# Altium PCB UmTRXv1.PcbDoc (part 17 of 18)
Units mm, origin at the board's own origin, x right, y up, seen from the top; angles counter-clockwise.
Board outline 172 x 113 mm, 6 copper layers (Top Layer, GND, MidLayer1, Mid-Layer 2, InternalPlane2, Bottom Layer); 766 components, 613 nets, 3008 pads, 1360 vias.
Unrouted connection lines stored in the file: 2.
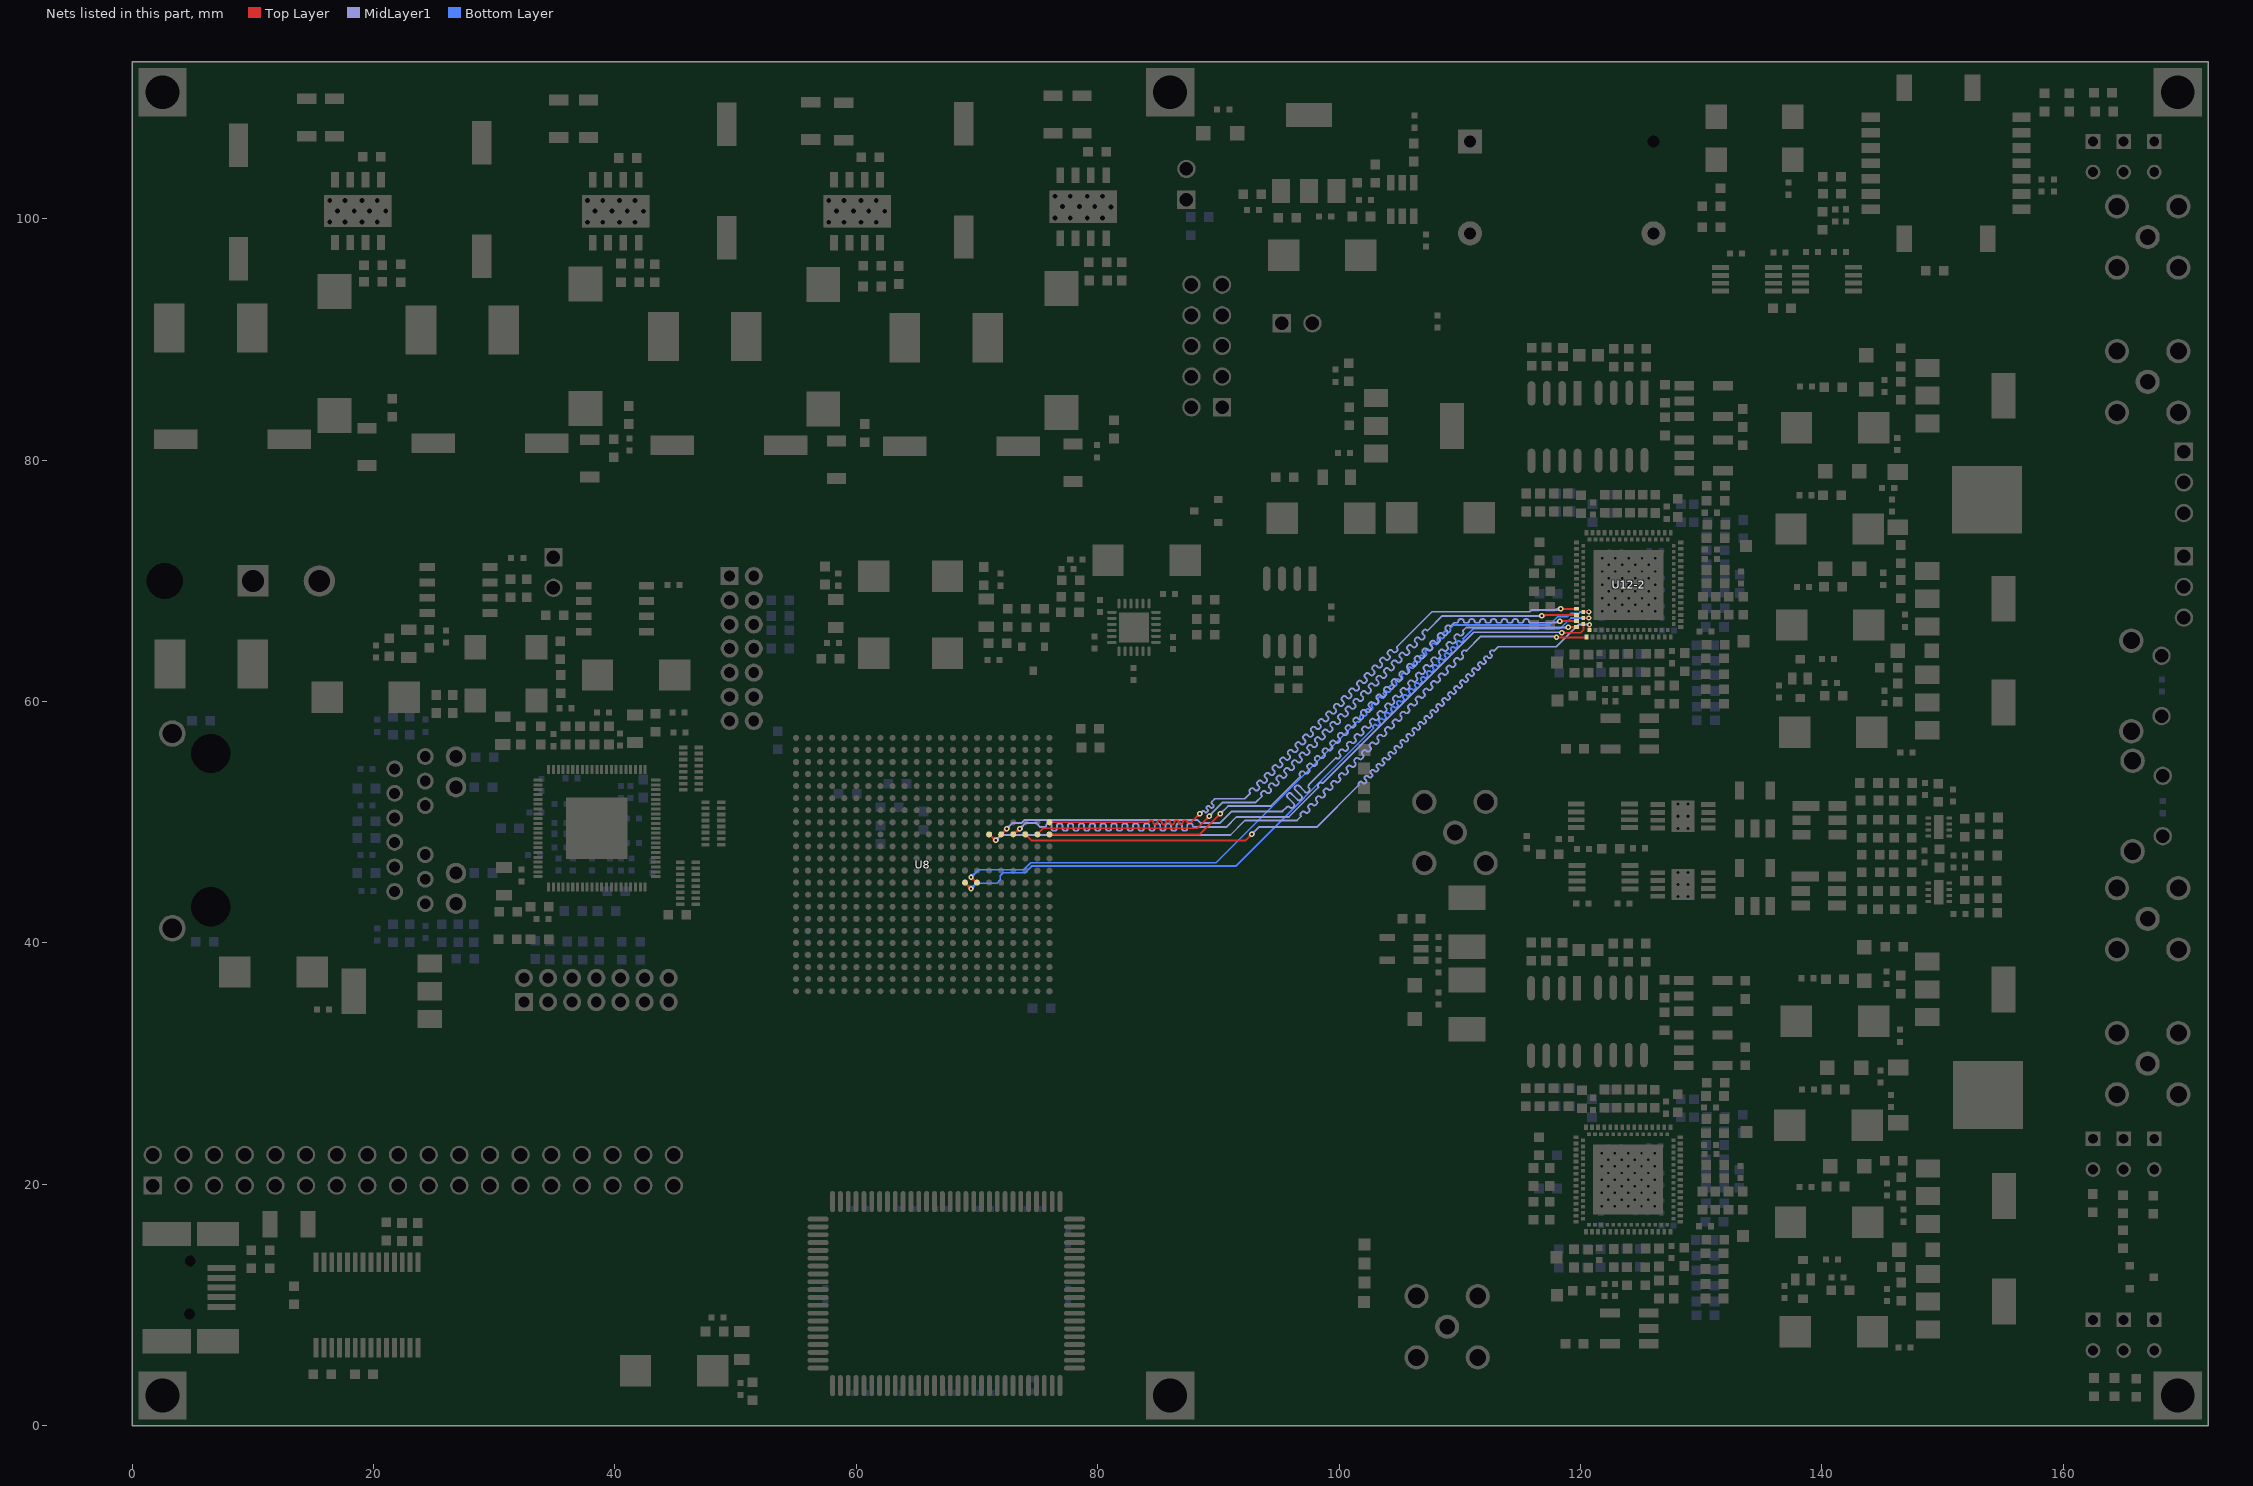
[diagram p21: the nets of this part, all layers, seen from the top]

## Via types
v1: diameter 0.45, hole 0.2, Top Layer to Bottom Layer, tented both sides, 554 vias
v2: diameter 0.5, hole 0.2, Top Layer to Bottom Layer, tented both sides, 468 vias
v3: diameter 0.7, hole 0.3, Top Layer to Bottom Layer, tented both sides, 206 vias
v4: diameter 0.4, hole 0.2, Top Layer to Bottom Layer, tented both sides, 82 vias
v5: diameter 0.8, hole 0.3, Top Layer to Bottom Layer, tented both sides, 16 vias
v6: diameter 0.6, hole 0.25, Top Layer to Bottom Layer, tented both sides, 16 vias
v7: diameter 0.5, hole 0.3, Top Layer to Bottom Layer, tented both sides, 8 vias
v8: diameter 0.7, hole 0.3, Top Layer to Bottom Layer, 4 vias
v9: diameter 0.6, hole 0.3, Top Layer to Bottom Layer, tented both sides, 4 vias
v10: diameter 0.5, hole 0.2, Top Layer to Bottom Layer, 2 vias

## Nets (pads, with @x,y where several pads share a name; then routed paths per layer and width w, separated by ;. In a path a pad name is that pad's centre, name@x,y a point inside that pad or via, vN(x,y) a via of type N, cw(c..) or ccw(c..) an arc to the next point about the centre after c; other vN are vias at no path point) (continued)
TX2D2: U8.R1 U12-2.23 | length 69.3
  Top Layer w0.15: U8.R1@76,50 84.25,50 cw(c84.425,50) 84.6,50 ccw(c84.775,50) 84.95,50 cw(c85.125,50) 85.3,50 ccw(c85.475,50) 85.65,50 cw(c85.825,50) 86,50 ccw(c86.175,50) 86.35,50 cw(c86.525,50) 86.7,50 ccw(c86.875,50) 87.05,50 cw(c87.225,50) 87.4,50 87.75,50 v1(88.45,50.7) ; v1@88.3,50.7 cw(c87.938,50.7) 88.194,50.444 cw(c88.45,50.188) v1@88.45,50.55 ; v1@118.335,67.68 U12-2.23@119.671,67.68 ; v1@118.456,67.594 cw(c118.664,67.386) 118.664,67.68 ; v1@118.456,67.806 ccw(c118.76,68.11) 118.76,67.68
  MidLayer1 w0.15: v1(88.45,50.7) 88.661,50.911 cw(c88.745,50.826) 88.83,50.911 88.887,50.854 ccw(c88.971,50.939) 89.056,50.854 89.099,50.897 ccw(c89.014,50.981) 89.099,51.066 89.042,51.123 cw(c89.127,51.208) 89.042,51.292 89.085,51.335 cw(c89.17,51.25) 89.254,51.335 89.368,51.222 ccw(c89.453,51.307) 89.537,51.222 89.58,51.264 ccw(c89.495,51.349) 89.58,51.434 89.467,51.547 cw(c89.552,51.632) 89.467,51.717 89.7,51.95 92.2,51.95 92.61,52.36 ccw(c92.56,52.409) 92.61,52.459 cw(c92.737,52.586) 92.61,52.713 92.673,52.777 cw(c92.801,52.65) 92.928,52.777 92.977,52.727 93.027,52.678 ccw(c93.154,52.805) 93.281,52.678 93.345,52.741 ccw(c93.218,52.869) 93.345,52.996 93.246,53.095 cw(c93.373,53.222) 93.246,53.35 93.31,53.413 cw(c93.437,53.286) 93.564,53.413 93.663,53.314 ccw(c93.79,53.441) 93.918,53.314 93.981,53.378 ccw(c93.854,53.505) 93.981,53.632 93.882,53.731 cw(c94.01,53.859) 93.882,53.986 93.946,54.05 cw(c94.073,53.922) 94.201,54.05 94.3,53.951 ccw(c94.427,54.078) 94.554,53.951 94.618,54.014 ccw(c94.49,54.142) 94.618,54.269 94.568,54.318 94.519,54.368 cw(c94.646,54.495) 94.519,54.622 94.582,54.686 cw(c94.71,54.559) 94.837,54.686 94.936,54.587 ccw(c95.063,54.714) 95.191,54.587 95.254,54.651 ccw(c95.127,54.778) 95.254,54.905 95.205,54.955 95.155,55.004 cw(c95.282,55.131) 95.155,55.259 95.219,55.322 cw(c95.346,55.195) 95.473,55.322 95.572,55.223 ccw(c95.7,55.351) 95.827,55.223 95.891,55.287 ccw(c95.763,55.414) 95.891,55.542 95.792,55.641 cw(c95.919,55.768) 95.792,55.895 95.855,55.959 cw(c95.982,55.831) 96.11,55.959 96.209,55.86 ccw(c96.336,55.987) 96.463,55.86 96.527,55.923 ccw(c96.4,56.051) 96.527,56.178 96.428,56.277 cw(c96.555,56.404) 96.428,56.532 96.492,56.595 cw(c96.619,56.468) 96.746,56.595 96.796,56.546 96.845,56.496 ccw(c96.972,56.623) 97.1,56.496 97.163,56.56 ccw(c97.036,56.687) 97.163,56.814 97.064,56.913 cw(c97.192,57.041) 97.064,57.168 97.128,57.232 cw(c97.255,57.104) 97.383,57.232 97.432,57.182 97.482,57.133 ccw(c97.609,57.26) 97.736,57.133 97.8,57.196 ccw(c97.672,57.323) 97.8,57.451 97.701,57.55 cw(c97.828,57.677) 97.701,57.804 97.764,57.868 cw(c97.892,57.741) 98.019,57.868 98.118,57.769 ccw(c98.245,57.896) 98.373,57.769 98.436,57.833 ccw(c98.309,57.96) 98.436,58.087 98.337,58.186 cw(c98.464,58.313) 98.337,58.441 98.401,58.504 cw(c98.528,58.377) 98.655,58.504 98.754,58.405 ccw(c98.882,58.533) 99.009,58.405 99.073,58.469 ccw(c98.945,58.596) 99.073,58.724 99.023,58.773 98.974,58.823 cw(c99.101,58.95) 98.974,59.077 99.037,59.141 cw(c99.164,59.013) 99.292,59.141 99.391,59.042 ccw(c99.518,59.169) 99.645,59.042 99.709,59.105 ccw(c99.582,59.233) 99.709,59.36 99.659,59.409 99.61,59.459 cw(c99.737,59.586) 99.61,59.713 99.674,59.777 cw(c99.801,59.65) 99.928,59.777 100.027,59.678 ccw(c100.154,59.805) 100.282,59.678 100.345,59.742 ccw(c100.218,59.869) 100.345,59.996 100.246,60.095 cw(c100.374,60.223) 100.246,60.35 100.31,60.414 cw(c100.437,60.286) 100.565,60.414 100.664,60.315 ccw(c100.791,60.442) 100.918,60.315 100.982,60.378 ccw(c100.854,60.505) 100.982,60.633 100.883,60.732 cw(c101.01,60.859) 100.883,60.986 100.946,61.05 cw(c101.074,60.923) 101.201,61.05 101.25,61 101.3,60.951 ccw(c101.427,61.078) 101.554,60.951 101.618,61.015 ccw(c101.491,61.142) 101.618,61.269 101.519,61.368 cw(c101.646,61.495) 101.519,61.623 101.583,61.686 cw(c101.71,61.559) 101.837,61.686 101.887,61.637 101.936,61.587 ccw(c102.064,61.715) 102.191,61.587 102.255,61.651 ccw(c102.127,61.778) 102.255,61.906 102.156,62.005 cw(c102.283,62.132) 102.156,62.259 102.219,62.323 cw(c102.346,62.195) 102.474,62.323 102.573,62.224 ccw(c102.7,62.351) 102.827,62.224 102.891,62.287 ccw(c102.764,62.415) 102.891,62.542 102.792,62.641 cw(c102.919,62.768) 102.792,62.895 102.856,62.959 cw(c102.983,62.832) 103.11,62.959 103.209,62.86 ccw(c103.336,62.987) 103.464,62.86 103.527,62.924 ccw(c103.4,63.051) 103.527,63.178 103.478,63.228 103.428,63.277 cw(c103.556,63.405) 103.428,63.532 103.492,63.596 cw(c103.619,63.468) 103.747,63.596 103.846,63.497 ccw(c103.973,63.624) 104.1,63.497 104.164,63.56 ccw(c104.036,63.687) 104.164,63.815 104.114,63.864 104.065,63.914 cw(c104.192,64.041) 104.065,64.168 104.128,64.232 cw(c104.256,64.105) 104.383,64.232 104.482,64.133 ccw(c104.609,64.26) 104.736,64.133 104.8,64.197 ccw(c104.673,64.324) 104.8,64.451 cw(c104.85,64.501) 104.8,64.55 107.7,67.45 115.81,67.45 115.951,67.591 118.335,67.591 118.35,67.605 v1(118.35,67.7) cw(c118.086,67.963) 118.086,67.591 ; v1@88.6,50.699 cw(c88.906,50.698) 88.754,50.964 ; 117.724,67.591 ccw(c117.724,68.326) v1@118.244,67.806
TX2D3: U8.K7 U12-2.24 | length 69.2
  Top Layer w0.15: v1@69.5,45.275 cw(c69.5,44.732) U8.K7@69.884,45.116 ; v1(69.5,45.45) 69.55,45.45 U8.K7@70,45 ; v1@69.675,45.45 ccw(c69.977,45.45) 69.763,45.237
  Top Layer w0.2: U12-2.24@120.246,67.43 v4@120.671,67.43 ; v4@120.625,67.359 ccw(c120.455,67.188) 120.455,67.43 ccw(c120.455,67.671) v4@120.625,67.501
  Bottom Layer w0.15: v1(69.5,45.45) 70.125,46.075 73.871,46.075 74.446,46.65 89.8,46.65 101.504,58.354 101.511,58.347 ccw(c101.61,58.446) 101.709,58.347 101.759,58.397 ccw(c101.66,58.496) 101.759,58.595 101.752,58.602 101.745,58.609 cw(c101.844,58.708) 101.745,58.807 101.794,58.856 cw(c101.893,58.757) 101.992,58.856 101.999,58.849 102.006,58.842 ccw(c102.105,58.941) 102.204,58.842 102.254,58.892 ccw(c102.155,58.991) 102.254,59.09 102.247,59.097 102.24,59.104 cw(c102.339,59.203) 102.24,59.302 102.289,59.351 cw(c102.388,59.252) 102.487,59.351 102.494,59.344 102.501,59.337 ccw(c102.6,59.436) 102.699,59.337 102.749,59.387 ccw(c102.65,59.486) 102.749,59.585 102.742,59.592 102.735,59.599 cw(c102.834,59.698) 102.735,59.797 102.784,59.846 cw(c102.883,59.747) 102.982,59.846 102.996,59.832 ccw(c103.095,59.931) 103.194,59.832 103.244,59.882 ccw(c103.145,59.981) 103.244,60.079 103.237,60.087 103.229,60.094 cw(c103.328,60.193) 103.229,60.292 103.279,60.341 cw(c103.378,60.242) 103.477,60.341 103.484,60.334 103.491,60.327 ccw(c103.59,60.426) 103.689,60.327 103.739,60.376 ccw(c103.64,60.475) 103.739,60.574 103.732,60.582 103.724,60.589 cw(c103.823,60.688) 103.724,60.787 103.774,60.836 cw(c103.873,60.737) 103.972,60.836 103.979,60.829 103.986,60.822 ccw(c104.085,60.921) 104.184,60.822 104.234,60.871 ccw(c104.135,60.97) 104.234,61.069 104.227,61.077 104.219,61.084 cw(c104.318,61.183) 104.219,61.282 104.269,61.331 cw(c104.368,61.232) 104.467,61.331 104.474,61.324 104.481,61.317 ccw(c104.58,61.416) 104.679,61.317 104.729,61.366 ccw(c104.63,61.465) 104.729,61.564 104.721,61.571 104.714,61.579 cw(c104.813,61.678) 104.714,61.777 104.764,61.826 cw(c104.863,61.727) 104.962,61.826 104.969,61.819 104.976,61.812 ccw(c105.075,61.911) 105.174,61.812 105.224,61.861 ccw(c105.125,61.96) 105.224,62.059 105.209,62.074 cw(c105.308,62.173) 105.209,62.272 105.259,62.321 cw(c105.358,62.222) 105.457,62.321 105.464,62.314 105.471,62.307 ccw(c105.57,62.406) 105.669,62.307 105.719,62.356 ccw(c105.62,62.455) 105.719,62.554 105.711,62.561 105.704,62.569 cw(c105.803,62.668) 105.704,62.767 105.754,62.816 cw(c105.853,62.717) 105.952,62.816 105.959,62.809 105.966,62.802 ccw(c106.065,62.901) 106.164,62.802 106.213,62.851 ccw(c106.114,62.95) 106.213,63.049 106.206,63.056 106.199,63.063 cw(c106.298,63.162) 106.199,63.261 106.249,63.311 cw(c106.348,63.212) 106.447,63.311 106.454,63.304 106.461,63.297 ccw(c106.56,63.396) 106.659,63.297 106.708,63.346 ccw(c106.609,63.445) 106.708,63.544 106.701,63.551 106.694,63.558 cw(c106.793,63.657) 106.694,63.756 106.744,63.806 cw(c106.843,63.707) 106.942,63.806 106.949,63.799 106.956,63.792 ccw(c107.055,63.891) 107.154,63.792 107.203,63.841 ccw(c107.104,63.94) 107.203,64.039 107.196,64.046 107.189,64.053 cw(c107.288,64.152) 107.189,64.251 107.239,64.301 cw(c107.338,64.202) 107.437,64.301 107.451,64.287 ccw(c107.55,64.386) 107.649,64.287 107.698,64.336 ccw(c107.599,64.435) 107.698,64.534 107.691,64.541 107.684,64.548 cw(c107.783,64.647) 107.684,64.746 107.734,64.796 cw(c107.833,64.697) 107.932,64.796 107.939,64.789 107.946,64.782 ccw(c108.045,64.881) 108.144,64.782 108.193,64.831 ccw(c108.094,64.93) 108.193,65.029 108.186,65.036 108.179,65.043 cw(c108.278,65.142) 108.179,65.241 108.229,65.291 cw(c108.328,65.192) 108.427,65.291 108.434,65.284 108.441,65.277 ccw(c108.54,65.376) 108.639,65.277 108.688,65.326 ccw(c108.589,65.425) 108.688,65.524 108.681,65.531 108.674,65.538 cw(c108.773,65.637) 108.674,65.736 108.724,65.786 cw(c108.823,65.687) 108.922,65.786 108.929,65.779 108.936,65.772 ccw(c109.035,65.871) 109.134,65.772 109.183,65.821 ccw(c109.084,65.92) 109.183,66.019 109.176,66.026 109.5,66.35 117.434,66.35 118.134,67.05 118.94,67.05 119.19,67.3 119.87,67.3 120,67.43 v4(120.696,67.43) ; v1@69.5,45.625 ccw(c69.5,46.047) 69.799,45.749 ccw(c70.097,45.45) v1@69.675,45.45 ; v4@120.608,67.341 ccw(c120.394,67.128) 120.394,67.43 ccw(c120.394,67.732) v4@120.608,67.518
TX2D4: U8.P2 U12-2.25 | length 69.2
  Top Layer w0.15: U8.P2@75,49 75.5,49.5 88.25,49.5 v1(89.25,50.5) ; v1@89.1,50.5 cw(c88.738,50.5) 88.994,50.244 cw(c89.25,49.988) v1@89.25,50.35 ; v1(116.8,67.1) 116.88,67.18 U12-2.25@119.671,67.18 ; v1@116.906,66.994 cw(c117.355,66.545) 117.355,67.18
  MidLayer1 w0.15: v1(89.25,50.5) 89.25,50.55 90.35,51.65 93.1,51.65 93.585,52.135 ccw(c93.535,52.184) 93.585,52.234 cw(c93.712,52.361) 93.585,52.488 93.648,52.552 cw(c93.776,52.425) 93.903,52.552 93.952,52.502 94.002,52.453 ccw(c94.129,52.58) 94.256,52.453 94.32,52.516 ccw(c94.193,52.644) 94.32,52.771 94.221,52.87 cw(c94.348,52.997) 94.221,53.125 94.285,53.188 cw(c94.412,53.061) 94.539,53.188 94.638,53.089 ccw(c94.765,53.216) 94.893,53.089 94.956,53.153 ccw(c94.829,53.28) 94.956,53.407 94.857,53.506 cw(c94.985,53.634) 94.857,53.761 94.921,53.825 cw(c95.048,53.697) 95.176,53.825 95.275,53.726 ccw(c95.402,53.853) 95.529,53.726 95.593,53.789 ccw(c95.466,53.917) 95.593,54.044 95.543,54.093 95.494,54.143 cw(c95.621,54.27) 95.494,54.397 95.557,54.461 cw(c95.685,54.334) 95.812,54.461 95.911,54.362 ccw(c96.038,54.489) 96.166,54.362 96.229,54.426 ccw(c96.102,54.553) 96.229,54.68 96.18,54.73 96.13,54.779 cw(c96.257,54.906) 96.13,55.034 96.194,55.097 cw(c96.321,54.97) 96.448,55.097 96.547,54.998 ccw(c96.675,55.126) 96.802,54.998 96.866,55.062 ccw(c96.738,55.189) 96.866,55.317 96.767,55.416 cw(c96.894,55.543) 96.767,55.67 96.83,55.734 cw(c96.957,55.606) 97.085,55.734 97.184,55.635 ccw(c97.311,55.762) 97.438,55.635 97.502,55.698 ccw(c97.375,55.826) 97.502,55.953 97.403,56.052 cw(c97.53,56.179) 97.403,56.307 97.467,56.37 cw(c97.594,56.243) 97.721,56.37 97.771,56.321 97.82,56.271 ccw(c97.947,56.398) 98.075,56.271 98.138,56.335 ccw(c98.011,56.462) 98.138,56.589 98.039,56.688 cw(c98.167,56.816) 98.039,56.943 98.103,57.007 cw(c98.23,56.879) 98.358,57.007 98.407,56.957 98.457,56.908 ccw(c98.584,57.035) 98.711,56.908 98.775,56.971 ccw(c98.647,57.098) 98.775,57.226 98.676,57.325 cw(c98.803,57.452) 98.676,57.579 98.739,57.643 cw(c98.867,57.516) 98.994,57.643 99.093,57.544 ccw(c99.22,57.671) 99.348,57.544 99.411,57.608 ccw(c99.284,57.735) 99.411,57.862 99.312,57.961 cw(c99.439,58.088) 99.312,58.216 99.376,58.279 cw(c99.503,58.152) 99.63,58.279 99.729,58.18 ccw(c99.857,58.308) 99.984,58.18 100.048,58.244 ccw(c99.92,58.371) 100.048,58.499 99.998,58.548 99.949,58.598 cw(c100.076,58.725) 99.949,58.852 100.012,58.916 cw(c100.139,58.788) 100.267,58.916 100.366,58.817 ccw(c100.493,58.944) 100.62,58.817 100.684,58.88 ccw(c100.557,59.008) 100.684,59.135 100.634,59.184 100.585,59.234 cw(c100.712,59.361) 100.585,59.488 100.649,59.552 cw(c100.776,59.425) 100.903,59.552 101.002,59.453 ccw(c101.129,59.58) 101.257,59.453 101.32,59.517 ccw(c101.193,59.644) 101.32,59.771 101.221,59.87 cw(c101.349,59.998) 101.221,60.125 101.285,60.189 cw(c101.412,60.061) 101.54,60.189 101.639,60.09 ccw(c101.766,60.217) 101.893,60.09 101.957,60.153 ccw(c101.829,60.28) 101.957,60.408 101.858,60.507 cw(c101.985,60.634) 101.858,60.761 101.921,60.825 cw(c102.049,60.698) 102.176,60.825 102.225,60.775 102.275,60.726 ccw(c102.402,60.853) 102.529,60.726 102.593,60.79 ccw(c102.466,60.917) 102.593,61.044 102.494,61.143 cw(c102.621,61.27) 102.494,61.398 102.558,61.461 cw(c102.685,61.334) 102.812,61.461 102.862,61.412 102.911,61.362 ccw(c103.039,61.49) 103.166,61.362 103.23,61.426 ccw(c103.102,61.553) 103.23,61.681 103.131,61.78 cw(c103.258,61.907) 103.131,62.034 103.194,62.098 cw(c103.321,61.97) 103.449,62.098 103.548,61.999 ccw(c103.675,62.126) 103.802,61.999 103.866,62.062 ccw(c103.739,62.19) 103.866,62.317 103.767,62.416 cw(c103.894,62.543) 103.767,62.67 103.831,62.734 cw(c103.958,62.607) 104.085,62.734 104.184,62.635 ccw(c104.311,62.762) 104.439,62.635 104.502,62.699 ccw(c104.375,62.826) 104.502,62.953 104.453,63.003 104.403,63.052 cw(c104.531,63.18) 104.403,63.307 104.467,63.371 cw(c104.594,63.243) 104.722,63.371 104.821,63.272 ccw(c104.948,63.399) 105.075,63.272 105.139,63.335 ccw(c105.011,63.462) 105.139,63.59 105.089,63.639 105.04,63.689 cw(c105.167,63.816) 105.04,63.943 105.103,64.007 cw(c105.231,63.88) 105.358,64.007 105.457,63.908 ccw(c105.584,64.035) 105.711,63.908 105.775,63.972 ccw(c105.648,64.099) 105.775,64.226 105.676,64.325 cw(c105.803,64.452) 105.676,64.58 105.74,64.643 cw(c105.867,64.516) 105.994,64.643 106.093,64.544 ; v1@89.25,50.65 ccw(c89.25,50.891) 89.421,50.721 ; v1@89.4,50.5 cw(c89.883,50.5) 89.541,50.841 ; 106.093,64.544 ccw(c106.221,64.672) 106.348,64.544 ; 106.348,64.544 106.411,64.608 ccw(c106.284,64.735) 106.411,64.862 106.312,64.961 cw(c106.44,65.089) 106.312,65.216 106.376,65.28 cw(c106.503,65.152) 106.631,65.28 106.68,65.23 106.73,65.181 ccw(c106.857,65.308) 106.984,65.181 107.048,65.244 ccw(c106.921,65.372) 107.048,65.499 106.949,65.598 cw(c107.076,65.725) 106.949,65.852 107.013,65.916 cw(c107.14,65.789) 107.267,65.916 ccw(c107.317,65.966) 107.366,65.916 108.55,67.1 v1(116.8,67.1) ; v1@116.694,66.994 ccw(c116.438,66.738) 116.438,67.1 ccw(c116.438,67.462) v1@116.694,67.206
TX2D5: U8.K8 U12-2.26 | length 69.4
  Top Layer w0.15: U8.K8@69,45 v1(69.5,44.5) ; v1@69.325,44.5 ccw(c68.903,44.5) 69.201,44.799 ccw(c69.5,45.098) v1@69.5,44.675
  Top Layer w0.2: U12-2.26@120.246,66.93 v4@120.671,66.93 ; v4@120.625,66.859 ccw(c120.455,66.688) 120.455,66.93 ccw(c120.455,67.171) v4@120.625,67.001
  Bottom Layer w0.15: v1(69.5,44.5) 69.95,44.95 71.651,44.95 71.925,45.224 71.925,45.575 72.175,45.825 73.975,45.825 74.525,46.375 91.425,46.375 102.852,57.802 102.845,57.809 cw(c102.944,57.908) 102.845,58.007 102.894,58.056 cw(c102.993,57.957) 103.092,58.056 103.099,58.049 103.106,58.042 ccw(c103.205,58.141) 103.304,58.042 103.354,58.092 ccw(c103.255,58.191) 103.354,58.29 103.347,58.297 103.34,58.304 cw(c103.439,58.403) 103.34,58.502 103.389,58.551 cw(c103.488,58.452) 103.587,58.551 103.594,58.544 103.601,58.537 ccw(c103.7,58.636) 103.799,58.537 103.849,58.587 ccw(c103.75,58.686) 103.849,58.785 103.842,58.792 103.835,58.799 cw(c103.934,58.898) 103.835,58.997 103.884,59.046 cw(c103.983,58.947) 104.082,59.046 104.096,59.032 ccw(c104.195,59.131) 104.294,59.032 104.344,59.082 ccw(c104.245,59.181) 104.344,59.279 104.337,59.287 104.329,59.294 cw(c104.428,59.393) 104.329,59.492 104.379,59.541 cw(c104.478,59.442) 104.577,59.541 104.584,59.534 104.591,59.527 ccw(c104.69,59.626) 104.789,59.527 104.839,59.576 ccw(c104.74,59.675) 104.839,59.774 104.832,59.782 104.824,59.789 cw(c104.923,59.888) 104.824,59.987 104.874,60.036 cw(c104.973,59.937) 105.072,60.036 105.079,60.029 105.086,60.022 ccw(c105.185,60.121) 105.284,60.022 105.334,60.071 ccw(c105.235,60.17) 105.334,60.269 105.327,60.277 105.319,60.284 cw(c105.418,60.383) 105.319,60.482 105.369,60.531 cw(c105.468,60.432) 105.567,60.531 105.574,60.524 105.581,60.517 ccw(c105.68,60.616) 105.779,60.517 105.829,60.566 ccw(c105.73,60.665) 105.829,60.764 105.821,60.771 105.814,60.779 cw(c105.913,60.878) 105.814,60.977 105.864,61.026 cw(c105.963,60.927) 106.062,61.026 106.069,61.019 106.076,61.012 ccw(c106.175,61.111) 106.274,61.012 106.324,61.061 ccw(c106.225,61.16) 106.324,61.259 106.309,61.274 cw(c106.408,61.373) 106.309,61.472 106.359,61.521 cw(c106.458,61.422) 106.557,61.521 106.564,61.514 106.571,61.507 ccw(c106.67,61.606) 106.769,61.507 106.819,61.556 ccw(c106.72,61.655) 106.819,61.754 106.811,61.761 106.804,61.769 cw(c106.903,61.868) 106.804,61.967 106.854,62.016 cw(c106.953,61.917) 107.052,62.016 107.059,62.009 107.066,62.002 ccw(c107.165,62.101) 107.264,62.002 107.313,62.051 ccw(c107.214,62.15) 107.313,62.249 107.306,62.256 107.299,62.263 cw(c107.398,62.362) 107.299,62.461 107.349,62.511 cw(c107.448,62.412) 107.547,62.511 107.554,62.504 107.561,62.497 ccw(c107.66,62.596) 107.759,62.497 107.808,62.546 ccw(c107.709,62.645) 107.808,62.744 107.801,62.751 107.794,62.758 cw(c107.893,62.857) 107.794,62.956 107.844,63.006 cw(c107.943,62.907) 108.042,63.006 108.049,62.999 108.056,62.992 ccw(c108.155,63.091) 108.254,62.992 108.303,63.041 ccw(c108.204,63.14) 108.303,63.239 108.296,63.246 108.289,63.253 cw(c108.388,63.352) 108.289,63.451 108.339,63.501 cw(c108.438,63.402) 108.537,63.501 108.551,63.487 ccw(c108.65,63.586) 108.749,63.487 108.798,63.536 ccw(c108.699,63.635) 108.798,63.734 108.791,63.741 108.784,63.748 cw(c108.883,63.847) 108.784,63.946 108.834,63.996 cw(c108.933,63.897) 109.032,63.996 109.039,63.989 109.046,63.982 ccw(c109.145,64.081) 109.244,63.982 109.293,64.031 ccw(c109.194,64.13) 109.293,64.229 109.286,64.236 109.279,64.243 cw(c109.378,64.342) 109.279,64.441 109.329,64.491 cw(c109.428,64.392) 109.527,64.491 109.534,64.484 109.541,64.477 ccw(c109.64,64.576) 109.739,64.477 109.788,64.526 ccw(c109.689,64.625) 109.788,64.724 109.781,64.731 109.774,64.738 cw(c109.873,64.837) 109.774,64.936 109.824,64.986 cw(c109.923,64.887) 110.022,64.986 110.029,64.979 110.036,64.972 ccw(c110.135,65.071) 110.234,64.972 110.283,65.021 ccw(c110.184,65.12) 110.283,65.219 110.276,65.226 111.1,66.05 118.234,66.05 118.284,66.1 118.384,66.1 119.214,66.93 v4(120.696,66.93) ; v1@69.5,44.675 ccw(c69.5,45.097) 69.799,44.799 ccw(c70.097,44.5) v1@69.675,44.5 ; v4@120.608,66.841 ccw(c120.394,66.628) 120.394,66.93 ccw(c120.394,67.232) v4@120.608,67.018
TX2D6: U8.P1 U12-2.27 | length 69.8
  Top Layer w0.15: U8.P1@76,49 88.45,49 v1(90.15,50.7) ; v1@90,50.7 cw(c89.638,50.7) 89.894,50.444 cw(c90.15,50.188) v1@90.15,50.55 ; v1(118.3,66.65) 118.304,66.65 118.414,66.541 118.5,66.7 118.48,66.68 U12-2.27@119.671,66.68 ; v1@118.406,66.544 cw(c118.734,66.216) 118.734,66.68 ; v1@118.406,66.756 ccw(c118.59,66.94) 118.59,66.68
  MidLayer1 w0.15: v1(90.15,50.7) 90.8,51.35 94.35,51.35 96.763,53.763 ccw(c96.714,53.813) 96.763,53.862 cw(c96.891,53.99) 96.763,54.117 96.827,54.181 cw(c96.954,54.053) 97.082,54.181 97.181,54.082 ccw(c97.308,54.209) 97.435,54.082 97.499,54.145 ccw(c97.371,54.272) 97.499,54.4 97.4,54.499 cw(c97.527,54.626) 97.4,54.753 97.463,54.817 cw(c97.591,54.69) 97.718,54.817 97.767,54.767 97.817,54.718 ccw(c97.944,54.845) 98.072,54.718 98.135,54.782 ccw(c98.008,54.909) 98.135,55.036 98.036,55.135 cw(c98.163,55.262) 98.036,55.39 98.1,55.453 cw(c98.227,55.326) 98.354,55.453 98.404,55.404 98.453,55.354 ccw(c98.581,55.482) 98.708,55.354 98.772,55.418 ccw(c98.644,55.545) 98.772,55.673 98.673,55.772 cw(c98.8,55.899) 98.673,56.026 98.736,56.09 cw(c98.863,55.962) 98.991,56.09 99.09,55.991 ccw(c99.217,56.118) 99.344,55.991 99.408,56.054 ccw(c99.281,56.182) 99.408,56.309 99.309,56.408 cw(c99.436,56.535) 99.309,56.663 99.373,56.726 cw(c99.5,56.599) 99.627,56.726 99.726,56.627 ccw(c99.853,56.754) 99.981,56.627 100.044,56.691 ccw(c99.917,56.818) 100.044,56.945 99.995,56.995 99.945,57.044 cw(c100.073,57.172) 99.945,57.299 100.009,57.363 cw(c100.136,57.235) 100.264,57.363 100.363,57.264 ccw(c100.49,57.391) 100.617,57.264 100.681,57.327 ccw(c100.553,57.454) 100.681,57.582 100.631,57.631 100.582,57.681 cw(c100.709,57.808) 100.582,57.935 100.645,57.999 cw(c100.773,57.872) 100.9,57.999 100.999,57.9 ccw(c101.126,58.027) 101.253,57.9 101.317,57.964 ccw(c101.19,58.091) 101.317,58.218 101.218,58.317 cw(c101.345,58.444) 101.218,58.572 101.282,58.635 cw(c101.409,58.508) 101.536,58.635 101.635,58.536 ccw(c101.763,58.664) 101.89,58.536 101.954,58.6 ccw(c101.826,58.727) 101.954,58.855 101.855,58.954 cw(c101.982,59.081) 101.855,59.208 101.918,59.272 cw(c102.045,59.144) 102.173,59.272 102.222,59.222 102.272,59.173 ccw(c102.399,59.3) 102.526,59.173 102.59,59.236 ccw(c102.463,59.364) 102.59,59.491 102.491,59.59 cw(c102.618,59.717) 102.491,59.844 102.555,59.908 cw(c102.682,59.781) 102.809,59.908 102.859,59.859 102.908,59.809 ccw(c103.035,59.936) 103.163,59.809 103.226,59.873 ccw(c103.099,60) 103.226,60.127 103.127,60.226 cw(c103.255,60.354) 103.127,60.481 103.191,60.545 cw(c103.318,60.417) 103.446,60.545 103.545,60.446 ccw(c103.672,60.573) 103.799,60.446 103.863,60.509 ccw(c103.735,60.636) 103.863,60.764 103.764,60.863 cw(c103.891,60.99) 103.764,61.117 103.827,61.181 cw(c103.955,61.054) 104.082,61.181 104.181,61.082 ccw(c104.308,61.209) 104.435,61.082 104.499,61.146 ccw(c104.372,61.273) 104.499,61.4 104.45,61.45 104.4,61.499 cw(c104.527,61.626) 104.4,61.754 104.464,61.817 cw(c104.591,61.69) 104.718,61.817 104.817,61.718 ccw(c104.945,61.846) 105.072,61.718 105.136,61.782 ccw(c105.008,61.909) 105.136,62.037 105.086,62.086 105.037,62.136 cw(c105.164,62.263) 105.037,62.39 105.1,62.454 cw(c105.227,62.326) 105.355,62.454 105.454,62.355 ccw(c105.581,62.482) 105.708,62.355 105.772,62.418 ccw(c105.645,62.546) 105.772,62.673 105.673,62.772 cw(c105.8,62.899) 105.673,63.026 105.737,63.09 cw(c105.864,62.963) 105.991,63.09 106.09,62.991 ccw(c106.217,63.118) 106.345,62.991 106.408,63.055 ccw(c106.281,63.182) 106.408,63.309 106.309,63.408 cw(c106.437,63.536) 106.309,63.663 106.373,63.726 cw(c106.5,63.599) 106.627,63.726 106.677,63.677 106.726,63.627 ccw(c106.854,63.755) 106.981,63.627 107.045,63.691 ccw(c106.917,63.818) 107.045,63.946 106.946,64.045 cw(c107.073,64.172) 106.946,64.299 107.009,64.363 cw(c107.137,64.236) 107.264,64.363 107.313,64.313 107.363,64.264 ccw(c107.49,64.391) 107.617,64.264 107.681,64.328 ccw(c107.554,64.455) 107.681,64.582 107.582,64.681 cw(c107.709,64.808) 107.582,64.936 107.646,64.999 cw(c107.773,64.872) 107.9,64.999 107.999,64.9 ccw(c108.127,65.028) 108.254,64.9 108.317,64.964 ccw(c108.19,65.091) 108.317,65.218 108.218,65.317 cw(c108.346,65.445) 108.218,65.572 108.282,65.636 cw(c108.409,65.508) 108.537,65.636 108.636,65.537 ccw(c108.763,65.664) 108.89,65.537 108.954,65.6 ccw(c108.827,65.728) 108.954,65.855 108.904,65.904 108.855,65.954 cw(c108.982,66.081) 108.855,66.208 108.919,66.272 cw(c109.046,66.145) 109.173,66.272 ccw(c109.223,66.322) 109.272,66.272 109.541,66.541 109.755,66.541 ccw(c109.755,66.661) 109.875,66.661 cw(c110.055,66.661) 110.055,66.841 110.145,66.841 cw(c110.145,66.661) 110.325,66.661 ccw(c110.445,66.661) 110.445,66.541 110.655,66.541 ccw(c110.655,66.661) 110.775,66.661 cw(c110.955,66.661) 110.955,66.841 111.045,66.841 cw(c111.045,66.661) 111.225,66.661 ccw(c111.345,66.661) 111.345,66.541 111.555,66.541 ccw(c111.555,66.661) 111.675,66.661 cw(c111.855,66.661) 111.855,66.841 111.945,66.841 cw(c111.945,66.661) 112.125,66.661 ccw(c112.245,66.661) 112.245,66.541 112.455,66.541 ccw(c112.455,66.661) 112.575,66.661 cw(c112.755,66.661) 112.755,66.841 112.845,66.841 cw(c112.845,66.661) 113.025,66.661 ccw(c113.145,66.661) 113.145,66.541 113.355,66.541 ccw(c113.355,66.661) 113.475,66.661 cw(c113.655,66.661) 113.655,66.841 113.745,66.841 cw(c113.745,66.661) 113.925,66.661 ccw(c114.045,66.661) 114.045,66.541 114.255,66.541 ccw(c114.255,66.661) 114.375,66.661 cw(c114.555,66.661) 114.555,66.841 114.645,66.841 cw(c114.645,66.661) 114.825,66.661 ccw(c114.945,66.661) 114.945,66.541 115.155,66.541 ccw(c115.155,66.661) 115.275,66.661 cw(c115.455,66.661) 115.455,66.841 115.545,66.841 cw(c115.545,66.661) 115.725,66.661 ccw(c115.845,66.661) 115.845,66.541 118.414,66.541 118.304,66.65 v1(118.3,66.65) cw(c118.036,66.913) 118.036,66.541 ; v1@90.15,50.85 ccw(c90.15,51.212) 90.406,50.956 ccw(c90.662,50.7) v1@90.3,50.7 ; 117.674,66.541 ccw(c117.674,67.276) v1@118.194,66.756
TX2D7: U8.P4 U12-2.28 | length 69.2
  Top Layer w0.15: U8.P4@73,49 73.5,49.5 v1(73.55,49.45) ; U8.P4@73.08,49.08 cw(c73.55,48.611) v1@73.55,49.275 ; 73.322,49.322 ccw(c73.194,49.45) v1@73.375,49.45 ; v1(118.45,65.7) 120.016,65.7 120.246,65.93 U12-2.28@120.246,66.43 ; v1@118.556,65.594 cw(c118.812,65.338) 118.812,65.7 cw(c118.812,66.062) v1@118.556,65.806
  MidLayer1 w0.15: v1@73.55,49.625 ccw(c73.55,50.047) 73.849,49.749 ccw(c74.147,49.45) v1@73.725,49.45 ; v1(73.55,49.45) 74.05,49.95 74.9,49.95 75.25,49.6 75.605,49.6 ccw(c75.605,49.72) 75.725,49.72 cw(c75.905,49.72) 75.905,49.9 75.995,49.9 cw(c75.995,49.72) 76.175,49.72 76.175,49.48 ccw(c76.355,49.48) 76.355,49.3 76.445,49.3 ccw(c76.445,49.48) 76.625,49.48 76.625,49.72 cw(c76.805,49.72) 76.805,49.9 76.895,49.9 cw(c76.895,49.72) 77.075,49.72 77.075,49.48 ccw(c77.255,49.48) 77.255,49.3 77.345,49.3 ccw(c77.345,49.48) 77.525,49.48 77.525,49.72 cw(c77.705,49.72) 77.705,49.9 77.795,49.9 cw(c77.795,49.72) 77.975,49.72 77.975,49.48 ccw(c78.155,49.48) 78.155,49.3 78.245,49.3 ccw(c78.245,49.48) 78.425,49.48 78.425,49.72 cw(c78.605,49.72) 78.605,49.9 78.695,49.9 cw(c78.695,49.72) 78.875,49.72 78.875,49.48 ccw(c79.055,49.48) 79.055,49.3 79.145,49.3 ccw(c79.145,49.48) 79.325,49.48 79.325,49.72 cw(c79.505,49.72) 79.505,49.9 79.595,49.9 cw(c79.595,49.72) 79.775,49.72 79.775,49.48 ccw(c79.955,49.48) 79.955,49.3 80.045,49.3 ccw(c80.045,49.48) 80.225,49.48 80.225,49.72 cw(c80.405,49.72) 80.405,49.9 80.495,49.9 cw(c80.495,49.72) 80.675,49.72 80.675,49.48 ccw(c80.855,49.48) 80.855,49.3 80.945,49.3 ccw(c80.945,49.48) 81.125,49.48 81.125,49.72 cw(c81.305,49.72) 81.305,49.9 81.395,49.9 cw(c81.395,49.72) 81.575,49.72 81.575,49.48 ccw(c81.755,49.48) 81.755,49.3 81.845,49.3 ccw(c81.845,49.48) 82.025,49.48 82.025,49.72 cw(c82.205,49.72) 82.205,49.9 82.295,49.9 cw(c82.295,49.72) 82.475,49.72 82.475,49.48 ccw(c82.655,49.48) 82.655,49.3 82.745,49.3 ccw(c82.745,49.48) 82.925,49.48 82.925,49.72 cw(c83.105,49.72) 83.105,49.9 83.195,49.9 cw(c83.195,49.72) 83.375,49.72 83.375,49.48 ccw(c83.555,49.48) 83.555,49.3 83.645,49.3 ccw(c83.645,49.48) 83.825,49.48 83.825,49.72 cw(c84.005,49.72) 84.005,49.9 84.095,49.9 cw(c84.095,49.72) 84.275,49.72 84.275,49.48 ccw(c84.455,49.48) 84.455,49.3 84.545,49.3 ccw(c84.545,49.48) 84.725,49.48 84.725,49.72 cw(c84.905,49.72) 84.905,49.9 84.995,49.9 cw(c84.995,49.72) 85.175,49.72 85.175,49.48 ccw(c85.355,49.48) 85.355,49.3 85.445,49.3 ccw(c85.445,49.48) 85.625,49.48 85.625,49.72 cw(c85.805,49.72) 85.805,49.9 85.895,49.9 cw(c85.895,49.72) 86.075,49.72 86.075,49.48 ccw(c86.255,49.48) 86.255,49.3 86.345,49.3 ccw(c86.345,49.48) 86.525,49.48 86.525,49.72 cw(c86.705,49.72) 86.705,49.9 86.795,49.9 cw(c86.795,49.72) 86.975,49.72 86.975,49.48 ccw(c87.155,49.48) 87.155,49.3 87.245,49.3 ccw(c87.245,49.48) 87.425,49.48 87.425,49.72 cw(c87.605,49.72) 87.605,49.9 87.695,49.9 cw(c87.695,49.72) 87.875,49.72 ccw(c87.995,49.72) 87.995,49.6 90.65,49.6 91.5,50.45 95.85,50.45 98.295,52.895 ccw(c98.281,52.909) 98.295,52.923 cw(c98.422,53.051) 98.295,53.178 98.359,53.241 cw(c98.486,53.114) 98.613,53.241 ccw(c98.627,53.256) 98.641,53.241 111.145,65.745 118.405,65.745 v1(118.45,65.7)
TX2D8: U8.P5 U12-2.29 | length 69.7
  Top Layer w0.15: U8.P5@72,49 v1(72.45,49.45) ; v1@72.275,49.45 cw(c71.853,49.45) 72.151,49.151 cw(c72.45,48.853) v1@72.45,49.275 ; v1(119,66.15) 119.03,66.18 U12-2.29@119.671,66.18 ; v1@119.106,66.044 cw(c119.434,65.716) 119.434,66.18 ; v1@119.106,66.256 ccw(c119.29,66.44) 119.29,66.18
  MidLayer1 w0.15: v1(72.45,49.45) 72.95,49.95 73.697,49.95 73.947,50.2 88.254,50.2 88.504,49.95 90.15,49.95 91.1,50.9 95.3,50.9 95.65,51.25 cw(c95.777,51.123) 95.905,51.25 95.923,51.231 ccw(c96.051,51.359) 96.178,51.231 96.241,51.295 ccw(c96.114,51.422) 96.241,51.55 96.095,51.695 95.728,52.063 cw(c95.855,52.19) 95.728,52.318 95.791,52.381 cw(c95.919,52.254) 96.046,52.381 96.414,52.014 96.56,51.868 ccw(c96.687,51.995) 96.814,51.868 96.878,51.931 ccw(c96.751,52.059) 96.878,52.186 96.732,52.332 96.364,52.7 cw(c96.491,52.827) 96.364,52.954 96.428,53.018 cw(c96.555,52.891) 96.682,53.018 97.05,52.65 97.196,52.504 ccw(c97.323,52.631) 97.451,52.504 97.514,52.568 ccw(c97.387,52.695) 97.514,52.822 97.496,52.841 cw(c97.623,52.968) 97.496,53.096 99.726,55.326 cw(c99.74,55.312) 99.755,55.326 ccw(c99.882,55.454) 100.009,55.326 100.073,55.39 ccw(c99.945,55.517) 100.073,55.644 100.059,55.659 100.044,55.673 cw(c100.172,55.8) 100.044,55.927 100.108,55.991 cw(c100.235,55.864) 100.363,55.991 100.377,55.977 100.391,55.963 ccw(c100.518,56.09) 100.645,55.963 100.709,56.026 ccw(c100.582,56.154) 100.709,56.281 100.695,56.295 100.681,56.309 cw(c100.808,56.436) 100.681,56.564 100.744,56.627 cw(c100.872,56.5) 100.999,56.627 101.013,56.613 101.027,56.599 ccw(c101.155,56.726) 101.282,56.599 101.346,56.663 ccw(c101.218,56.79) 101.346,56.917 101.317,56.946 cw(c101.445,57.073) 101.317,57.2 101.381,57.264 cw(c101.508,57.136) 101.635,57.264 101.65,57.25 101.664,57.235 ccw(c101.791,57.363) 101.918,57.235 101.982,57.299 ccw(c101.855,57.426) 101.982,57.554 101.968,57.568 101.954,57.582 cw(c102.081,57.709) 101.954,57.836 102.017,57.9 cw(c102.145,57.773) 102.272,57.9 102.286,57.886 102.3,57.872 ccw(c102.427,57.999) 102.555,57.872 102.618,57.935 ccw(c102.491,58.063) 102.618,58.19 102.604,58.204 102.59,58.218 cw(c102.717,58.346) 102.59,58.473 102.654,58.537 cw(c102.781,58.409) 102.908,58.537 102.922,58.522 102.937,58.508 ccw(c103.064,58.635) 103.191,58.508 103.255,58.572 ccw(c103.127,58.699) 103.255,58.826 103.241,58.841 103.226,58.855 cw(c103.354,58.982) 103.226,59.109 103.29,59.173 cw(c103.417,59.046) 103.545,59.173 103.559,59.159 103.573,59.145 ccw(c103.7,59.272) 103.827,59.145 103.891,59.208 ccw(c103.764,59.336) 103.891,59.463 103.877,59.477 103.863,59.491 cw(c103.99,59.618) 103.863,59.746 103.926,59.809 cw(c104.054,59.682) 104.181,59.809 104.195,59.795 104.209,59.781 ccw(c104.337,59.908) 104.464,59.781 104.527,59.845 ccw(c104.4,59.972) 104.527,60.099 104.513,60.113 104.499,60.127 cw(c104.626,60.255) 104.499,60.382 104.563,60.446 cw(c104.69,60.318) 104.817,60.446 104.832,60.432 104.846,60.417 ccw(c104.973,60.545) 105.1,60.417 105.164,60.481 ccw(c105.037,60.608) 105.164,60.736 105.15,60.75 105.136,60.764 cw(c105.263,60.891) 105.136,61.018 105.199,61.082 cw(c105.327,60.955) 105.454,61.082 105.468,61.068 105.482,61.054 ccw(c105.609,61.181) 105.737,61.054 105.8,61.117 ccw(c105.673,61.245) 105.8,61.372 105.786,61.386 105.772,61.4 cw(c105.899,61.528) 105.772,61.655 105.836,61.718 cw(c105.963,61.591) 106.09,61.718 106.104,61.704 106.118,61.69 ccw(c106.246,61.817) 106.373,61.69 106.437,61.754 ccw(c106.309,61.881) 106.437,62.008 106.423,62.023 106.408,62.037 cw(c106.536,62.164) 106.408,62.291 106.472,62.355 cw(c106.599,62.228) 106.727,62.355 106.741,62.341 106.755,62.327 ccw(c106.882,62.454) 107.009,62.327 107.073,62.39 ccw(c106.946,62.518) 107.073,62.645 107.059,62.659 107.045,62.673 cw(c107.172,62.8) 107.045,62.928 107.108,62.991 cw(c107.236,62.864) 107.363,62.991 107.377,62.977 107.391,62.963 ccw(c107.519,63.09) 107.646,62.963 107.709,63.027 ccw(c107.582,63.154) 107.709,63.281 107.695,63.295 107.681,63.309 cw(c107.808,63.437) 107.681,63.564 107.745,63.628 cw(c107.872,63.5) 107.999,63.628 108.014,63.614 108.028,63.599 ccw(c108.155,63.727) 108.282,63.599 108.346,63.663 ccw(c108.219,63.79) 108.346,63.918 108.332,63.932 108.318,63.946 cw(c108.445,64.073) 108.318,64.2 108.381,64.264 cw(c108.508,64.137) 108.636,64.264 108.65,64.25 108.664,64.236 ccw(c108.791,64.363) 108.919,64.236 108.982,64.299 ccw(c108.855,64.427) 108.982,64.554 108.968,64.568 108.954,64.582 cw(c109.081,64.71) 108.954,64.837 109.018,64.9 cw(c109.145,64.773) 109.272,64.9 109.286,64.886 109.3,64.872 ccw(c109.428,64.999) 109.555,64.872 109.619,64.936 ccw(c109.491,65.063) 109.619,65.19 109.605,65.205 109.59,65.219 cw(c109.718,65.346) 109.59,65.473 109.654,65.537 cw(c109.781,65.41) 109.909,65.537 109.923,65.523 109.937,65.509 ccw(c110.064,65.636) 110.191,65.509 110.255,65.572 ccw(c110.128,65.699) 110.255,65.827 cw(c110.269,65.841) 110.255,65.855 110.541,66.141 118.991,66.141 v1(119,66.15) ; v1@72.45,49.625 ccw(c72.45,50.047) 72.749,49.749 ccw(c73.047,49.45) v1@72.625,49.45 ; 118.616,66.141 ccw(c118.616,66.534) v1@118.894,66.256 ; 118.66,66.141 cw(c118.66,65.81) v1@118.894,66.044
TX2D9: U8.P6 U12-2.30 | length 68.6
  Top Layer w0.15: U8.P6@71,49 71.5,48.5 v1(71.55,48.5) ; U8.P6@71.166,48.834 ccw(c71.55,49.218) v1@71.55,48.675 ; 71.287,48.713 cw(c71.073,48.5) v1@71.375,48.5 ; v1(118.013,65.345) 118.059,65.3 120.441,65.3 U12-2.30@120.496,65.355
  MidLayer1 w0.15: v1(71.55,48.5) 71.995,48.945 ; v1@71.55,48.675 ccw(c71.55,49.097) 71.849,48.799 ccw(c72.147,48.5) v1@71.725,48.5 ; 71.995,48.95 91,48.95 92.2,50.15 96.5,50.15 96.845,50.495 ccw(c96.831,50.509) 96.845,50.523 cw(c96.972,50.651) 96.845,50.778 96.909,50.841 cw(c97.036,50.714) 97.163,50.841 97.177,50.827 97.191,50.813 ccw(c97.319,50.94) 97.446,50.813 97.51,50.877 ccw(c97.382,51.004) 97.51,51.131 97.495,51.145 97.481,51.16 cw(c97.609,51.287) 97.481,51.414 97.545,51.478 cw(c97.672,51.351) 97.8,51.478 97.814,51.464 97.828,51.45 ccw(c97.955,51.577) 98.082,51.45 98.146,51.513 ccw(c98.019,51.64) 98.146,51.768 98.132,51.782 98.118,51.796 cw(c98.245,51.923) 98.118,52.051 98.181,52.114 cw(c98.309,51.987) 98.436,52.114 98.45,52.1 98.464,52.086 ccw(c98.592,52.213) 98.719,52.086 98.782,52.15 ccw(c98.655,52.277) 98.782,52.404 98.768,52.418 98.754,52.432 cw(c98.881,52.56) 98.754,52.687 98.818,52.751 cw(c98.945,52.623) 99.072,52.751 99.086,52.736 99.101,52.722 ccw(c99.228,52.85) 99.355,52.722 99.419,52.786 ccw(c99.292,52.913) 99.419,53.041 99.405,53.055 99.391,53.069 cw(c99.518,53.196) 99.391,53.323 99.454,53.387 cw(c99.581,53.26) 99.709,53.387 99.723,53.373 99.737,53.359 ccw(c99.864,53.486) 99.992,53.359 100.055,53.422 ccw(c99.928,53.55) 100.055,53.677 100.041,53.691 100.027,53.705 cw(c100.154,53.832) 100.027,53.96 100.091,54.023 cw(c100.218,53.896) 100.345,54.023 100.359,54.009 100.373,53.995 ccw(c100.501,54.122) 100.628,53.995 100.692,54.059 ccw(c100.564,54.186) 100.692,54.313 100.677,54.327 100.663,54.342 cw(c100.791,54.469) 100.663,54.596 100.727,54.66 cw(c100.854,54.533) 100.982,54.66 100.996,54.646 101.01,54.632 ccw(c101.137,54.759) 101.264,54.632 101.328,54.695 ccw(c101.201,54.822) 101.328,54.95 101.314,54.964 101.3,54.978 cw(c101.427,55.105) 101.3,55.233 101.363,55.296 cw(c101.491,55.169) 101.618,55.296 101.632,55.282 101.646,55.268 ccw(c101.773,55.395) 101.901,55.268 101.964,55.332 ccw(c101.837,55.459) 101.964,55.586 101.95,55.6 101.936,55.614 cw(c102.063,55.742) 101.936,55.869 102,55.933 cw(c102.127,55.805) 102.254,55.933 102.268,55.918 102.283,55.904 ccw(c102.41,56.032) 102.537,55.904 102.601,55.968 ccw(c102.474,56.095) 102.601,56.223 102.587,56.237 102.573,56.251 cw(c102.7,56.378) 102.573,56.505 102.636,56.569 cw(c102.763,56.442) 102.891,56.569 102.905,56.555 102.919,56.541 ccw(c103.046,56.668) 103.174,56.541 103.237,56.604 ccw(c103.11,56.732) 103.237,56.859 103.223,56.873 103.209,56.887 cw(c103.336,57.014) 103.209,57.142 103.273,57.205 cw(c103.4,57.078) 103.527,57.205 103.541,57.191 103.555,57.177 ccw(c103.683,57.304) 103.81,57.177 103.874,57.241 ccw(c103.746,57.368) 103.874,57.495 103.859,57.509 103.845,57.524 cw(c103.973,57.651) 103.845,57.778 103.909,57.842 cw(c104.036,57.715) 104.163,57.842 104.178,57.828 104.192,57.813 ccw(c104.319,57.941) 104.446,57.813 104.51,57.877 ccw(c104.383,58.004) 104.51,58.132 104.496,58.146 104.482,58.16 cw(c104.609,58.287) 104.482,58.415 104.545,58.478 cw(c104.673,58.351) 104.8,58.478 104.814,58.464 104.828,58.45 ccw(c104.955,58.577) 105.083,58.45 105.146,58.514 ccw(c105.019,58.641) 105.146,58.768 105.132,58.782 105.118,58.796 cw(c105.245,58.924) 105.118,59.051 105.182,59.115 cw(c105.309,58.987) 105.436,59.115 105.45,59.1 105.465,59.086 ccw(c105.592,59.214) 105.719,59.086 105.783,59.15 ccw(c105.655,59.277) 105.783,59.404 105.754,59.433 cw(c105.882,59.56) 105.754,59.687 105.818,59.751 cw(c105.945,59.624) 106.073,59.751 106.087,59.737 106.101,59.723 ccw(c106.228,59.85) 106.356,59.723 106.419,59.786 ccw(c106.292,59.914) 106.419,60.041 106.405,60.055 106.391,60.069 cw(c106.518,60.196) 106.391,60.324 106.455,60.387 cw(c106.582,60.26) 106.709,60.387 106.723,60.373 106.737,60.359 ccw(c106.865,60.486) 106.992,60.359 107.056,60.423 ccw(c106.928,60.55) 107.056,60.677 107.041,60.691 107.027,60.706 cw(c107.155,60.833) 107.027,60.96 107.091,61.024 cw(c107.218,60.896) 107.345,61.024 107.36,61.01 107.374,60.995 ccw(c107.501,61.123) 107.628,60.995 107.692,61.059 ccw(c107.565,61.186) 107.692,61.314 107.678,61.328 107.664,61.342 cw(c107.791,61.469) 107.664,61.597 107.727,61.66 cw(c107.855,61.533) 107.982,61.66 108.01,61.632 ccw(c108.137,61.759) 108.265,61.632 108.328,61.696 ccw(c108.201,61.823) 108.328,61.95 108.314,61.964 108.3,61.978 cw(c108.427,62.106) 108.3,62.233 108.364,62.297 cw(c108.491,62.169) 108.618,62.297 108.632,62.282 108.647,62.268 ccw(c108.774,62.396) 108.901,62.268 108.965,62.332 ccw(c108.837,62.459) 108.965,62.586 108.951,62.601 108.936,62.615 cw(c109.064,62.742) 108.936,62.869 109,62.933 cw(c109.127,62.806) 109.255,62.933 109.269,62.919 109.283,62.905 ccw(c109.41,63.032) 109.537,62.905 109.601,62.968 ccw(c109.474,63.096) 109.601,63.223 109.587,63.237 109.573,63.251 cw(c109.7,63.378) 109.573,63.506 109.636,63.569 cw(c109.764,63.442) 109.891,63.569 109.905,63.555 109.919,63.541 ccw(c110.047,63.668) 110.174,63.541 110.238,63.605 ccw(c110.11,63.732) 110.238,63.859 110.209,63.888 cw(c110.337,64.015) 110.209,64.142 110.273,64.206 cw(c110.4,64.078) 110.527,64.206 ccw(c110.542,64.22) 110.556,64.206 111.748,65.398 117.96,65.398 v1(118.013,65.345)
TX2D10: U8.P3 U12-2.31 | length 69.2
  Top Layer w0.15: U8.P3@74,49 74.5,48.5 92.25,48.5 v1(92.75,49) ; v1@92.6,49 cw(c92.238,49) 92.494,48.744 cw(c92.75,48.488) v1@92.75,48.85
  Top Layer w0.2: v4@120.675,66.309 cw(c120.505,66.138) 120.746,66.138 cw(c120.987,66.138) v4@120.817,66.309 ; U12-2.31@120.746,65.93 v4@120.746,66.355
  MidLayer1 w0.15: v1(92.75,49) 93.35,49.6 98.15,49.6 101.6,53.05 101.6,53.15 101.602,53.152 ; v1@92.75,49.15 ccw(c92.75,49.512) 93.006,49.256 ccw(c93.262,49) v1@92.9,49 ; 101.61,53.152 cw(c101.747,53.182) 101.648,53.281 101.697,53.33 cw(c101.796,53.231) 101.895,53.33 101.98,53.245 ccw(c102.079,53.344) 102.178,53.245 102.228,53.295 ccw(c102.129,53.394) 102.228,53.493 102.143,53.578 cw(c102.242,53.677) 102.143,53.776 102.192,53.825 cw(c102.291,53.726) 102.39,53.825 102.475,53.74 ccw(c102.574,53.839) 102.673,53.74 102.723,53.79 ccw(c102.624,53.889) 102.723,53.988 102.638,54.073 cw(c102.737,54.172) 102.638,54.271 102.687,54.32 cw(c102.786,54.221) 102.885,54.32 102.97,54.235 ccw(c103.069,54.334) 103.168,54.235 103.218,54.285 ccw(c103.119,54.384) 103.218,54.483 103.133,54.568 cw(c103.232,54.667) 103.133,54.766 103.182,54.815 cw(c103.281,54.716) 103.38,54.815 103.465,54.73 ccw(c103.564,54.829) 103.663,54.73 103.713,54.78 ccw(c103.614,54.879) 103.713,54.978 103.628,55.063 cw(c103.727,55.162) 103.628,55.261 103.677,55.31 cw(c103.776,55.211) 103.875,55.31 103.96,55.225 ccw(c104.059,55.324) 104.158,55.225 104.208,55.275 ccw(c104.109,55.374) 104.208,55.473 104.123,55.558 cw(c104.222,55.657) 104.123,55.756 104.172,55.805 cw(c104.271,55.706) 104.37,55.805 104.455,55.72 ccw(c104.554,55.819) 104.653,55.72 104.702,55.77 ccw(c104.603,55.869) 104.702,55.968 104.618,56.052 cw(c104.717,56.151) 104.618,56.25 104.667,56.3 cw(c104.766,56.201) 104.865,56.3 104.95,56.215 ccw(c105.049,56.314) 105.148,56.215 105.197,56.265 ccw(c105.098,56.364) 105.197,56.463 105.113,56.547 cw(c105.212,56.646) 105.113,56.745 105.162,56.795 cw(c105.261,56.696) 105.36,56.795 105.445,56.71 ccw(c105.544,56.809) 105.643,56.71 105.692,56.76 ccw(c105.593,56.859) 105.692,56.958 105.608,57.042 cw(c105.707,57.141) 105.608,57.24 105.657,57.29 cw(c105.756,57.191) 105.855,57.29 105.94,57.205 ccw(c106.039,57.304) 106.138,57.205 106.187,57.255 ccw(c106.088,57.354) 106.187,57.453 106.103,57.537 cw(c106.202,57.636) 106.103,57.735 106.152,57.785 cw(c106.251,57.686) 106.35,57.785 106.435,57.7 ccw(c106.534,57.799) 106.633,57.7 106.682,57.75 ccw(c106.583,57.849) 106.682,57.948 106.598,58.032 cw(c106.697,58.131) 106.598,58.23 106.647,58.28 cw(c106.746,58.181) 106.845,58.28 106.93,58.195 ccw(c107.029,58.294) 107.128,58.195 107.177,58.245 ccw(c107.078,58.344) 107.177,58.443 107.093,58.527 cw(c107.191,58.626) 107.093,58.725 107.142,58.775 cw(c107.241,58.676) 107.34,58.775 107.425,58.69 ccw(c107.524,58.789) 107.623,58.69 107.672,58.739 ccw(c107.573,58.838) 107.672,58.937 107.587,59.022 cw(c107.686,59.121) 107.587,59.22 107.637,59.27 cw(c107.736,59.171) 107.835,59.27 107.92,59.185 ccw(c108.019,59.284) 108.118,59.185 108.167,59.234 ccw(c108.068,59.333) 108.167,59.432 108.082,59.517 cw(c108.181,59.616) 108.082,59.715 108.132,59.765 cw(c108.231,59.666) 108.33,59.765 108.415,59.68 ccw(c108.514,59.779) 108.613,59.68 108.662,59.729 ccw(c108.563,59.828) 108.662,59.927 108.577,60.012 cw(c108.676,60.111) 108.577,60.21 108.627,60.26 cw(c108.726,60.161) 108.825,60.26 108.91,60.175 ccw(c109.009,60.274) 109.108,60.175 109.157,60.224 ccw(c109.058,60.323) 109.157,60.422 109.072,60.507 cw(c109.171,60.606) 109.072,60.705 109.122,60.755 cw(c109.221,60.656) 109.32,60.755 109.405,60.67 ccw(c109.504,60.769) 109.603,60.67 109.652,60.719 ccw(c109.553,60.818) 109.652,60.917 109.567,61.002 cw(c109.666,61.101) 109.567,61.2 109.617,61.25 cw(c109.716,61.151) 109.815,61.25 109.9,61.165 ccw(c109.999,61.264) 110.098,61.165 110.147,61.214 ccw(c110.048,61.313) 110.147,61.412 110.062,61.497 cw(c110.161,61.596) 110.062,61.695 110.112,61.745 cw(c110.211,61.646) 110.31,61.745 110.395,61.66 ccw(c110.494,61.759) 110.593,61.66 110.642,61.709 ccw(c110.543,61.808) 110.642,61.907 110.557,61.992 cw(c110.656,62.091) 110.557,62.19 110.607,62.24 cw(c110.706,62.141) 110.805,62.24 110.89,62.155 ccw(c110.989,62.254) 111.088,62.155 111.137,62.204 ccw(c111.038,62.303) 111.137,62.402 111.052,62.487 cw(c111.151,62.586) 111.052,62.685 111.102,62.735 cw(c111.201,62.636) 111.3,62.735 111.385,62.65 ccw(c111.484,62.749) 111.583,62.65 111.632,62.699 ccw(c111.533,62.798) 111.632,62.897 111.547,62.982 cw(c111.646,63.081) 111.547,63.18 111.597,63.23 cw(c111.696,63.131) 111.795,63.23 111.88,63.145 ccw(c111.979,63.244) 112.078,63.145 112.127,63.194 ccw(c112.028,63.293) 112.127,63.392 112.042,63.477 cw(c112.141,63.576) 112.042,63.675 112.092,63.725 cw(c112.191,63.626) 112.29,63.725 112.375,63.64 ccw(c112.474,63.739) 112.573,63.64 112.622,63.689 ccw(c112.523,63.788) 112.622,63.887 112.537,63.972 cw(c112.636,64.071) 112.537,64.17 112.587,64.22 cw(c112.686,64.121) 112.785,64.22 ccw(c112.827,64.262) 112.87,64.22 113.198,64.548 118,64.548 119.831,66.38 v4(120.746,66.38) ; v4@120.658,66.291 ccw(c120.444,66.078) 120.444,66.38 ccw(c120.444,66.682) v4@120.658,66.468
